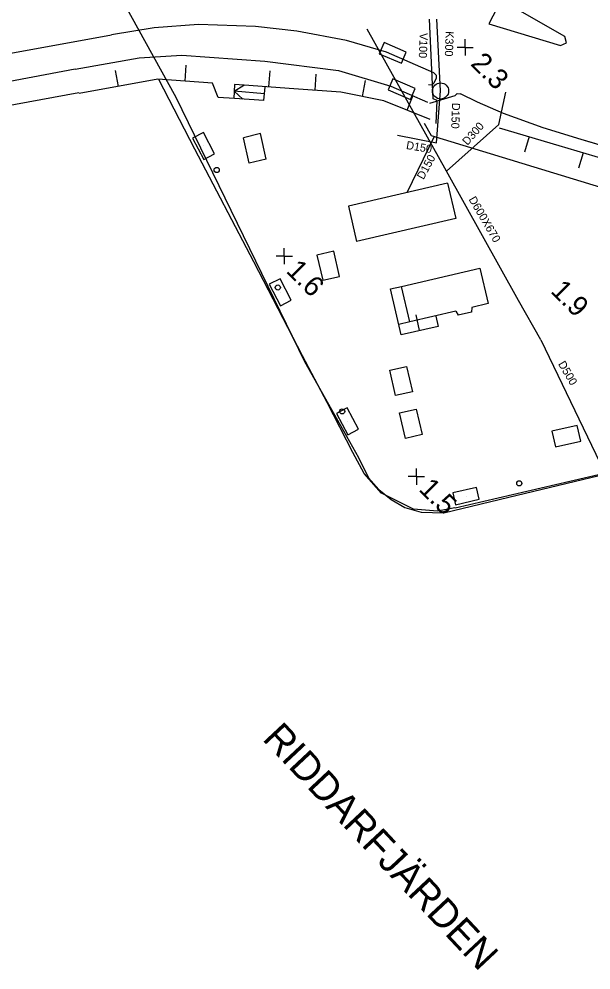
# Model space of a CAD drawing. Extents: x 1596643 to 1597288, y 13057194 to 13057957.
# Drawn here: x 1596788 to 1596858.8, y 13057321.4 to 13057439.2 of the extents above; entities that cross this region are included whole.
import ezdxf

# ---------------------------------------------------------------- set-up
doc = ezdxf.new("R2010")
doc.units = 0
for name, color, linetype in [('BAS bro ej def L', 7, 'Continuous'), ('BAS byggnad anläggning L', 7, 'Continuous'), ('BAS dagvatten brunn P', 7, 'Continuous'), ('BAS dagvatten ledning L', 7, 'Continuous'), ('BAS dagvatten ledning T', 7, 'Continuous'), ('BAS fastighetsgräns samfällighet L', 7, 'Continuous'), ('BAS kajkant L', 7, 'Continuous'), ('BAS Level 16', 7, 'Continuous'), ('BAS Level 18', 7, 'Continuous'), ('BAS Level 29', 7, 'Continuous'), ('BAS Level 34', 7, 'Continuous'), ('BAS markytetext T', 7, 'Continuous'), ('BAS spillvatten nedst brunn P', 7, 'Continuous'), ('BAS stödmur krön L', 7, 'Continuous'), ('BAS trappa L', 7, 'Continuous'), ('BAS vatten ledning L', 7, 'Continuous'), ('BAS vatten ledning T', 7, 'Continuous'), ('BAS vägbanekant L', 7, 'Continuous'), ('D el-anläggning ej def L', 7, 'Continuous')]:
    doc.layers.add(name, color=color, linetype=linetype)

msp = doc.modelspace()

# ---------------------------------------------------------------- linework, layer by layer
at = {"layer": 'BAS bro ej def L'}
msp.add_lwpolyline([(1596705.32, 13057413.45), (1596795.42, 13057430.04)], dxfattribs=at)
at = {"layer": 'BAS byggnad anläggning L'}
for p, q in [((1596817.89, 13057424.96), (1596815.8, 13057424.46)), ((1596816.51, 13057421.31), (1596815.8, 13057424.46)), ((1596818.61, 13057421.81), (1596817.89, 13057424.96)), ((1596818.61, 13057421.81), (1596816.51, 13057421.31)), ((1596841.05, 13057418.83), (1596828.79, 13057415.97)), ((1596841.05, 13057418.83), (1596842.07, 13057414.46)), ((1596828.79, 13057415.97), (1596829.8, 13057411.6)), ((1596842.07, 13057414.46), (1596829.8, 13057411.6)), ((1596826.97, 13057410.42), (1596824.87, 13057409.93)), ((1596827.67, 13057407.28), (1596826.97, 13057410.42)), ((1596824.87, 13057409.93), (1596825.6, 13057406.82)), ((1596835.34, 13057406.04), (1596845.06, 13057408.29)), ((1596845.06, 13057408.29), (1596846.07, 13057403.92)), ((1596825.6, 13057406.82), (1596827.67, 13057407.28)), ((1596836.37, 13057401.67), (1596835.34, 13057406.04)), ((1596842.06, 13057402.98), (1596836.37, 13057401.67)), ((1596842.06, 13057402.98), (1596842.37, 13057402.48)), ((1596844.06, 13057403.44), (1596844, 13057402.86)), ((1596846.07, 13057403.92), (1596844.06, 13057403.44)), ((1596844, 13057402.86), (1596842.37, 13057402.48)), ((1596833.89, 13057395.67), (1596835.97, 13057396.13)), ((1596835.97, 13057396.13), (1596836.7, 13057393.01)), ((1596834.61, 13057392.52), (1596833.89, 13057395.67)), ((1596836.7, 13057393.01), (1596834.61, 13057392.52)), ((1596835.11, 13057390.39), (1596837.18, 13057390.86)), ((1596835.86, 13057387.23), (1596835.11, 13057390.39)), ((1596837.18, 13057390.86), (1596837.92, 13057387.73)), ((1596857.09, 13057388.82), (1596853.98, 13057388.11)), ((1596857.53, 13057386.89), (1596857.09, 13057388.82)), ((1596837.92, 13057387.73), (1596835.86, 13057387.23)), ((1596853.98, 13057388.11), (1596854.42, 13057386.17)), ((1596854.42, 13057386.17), (1596857.53, 13057386.89))]:
    msp.add_line(p, q, dxfattribs=at)
msp.add_lwpolyline([(1596841.43, 13057417.48), (1596841.41, 13057417.48), (1596841.41, 13057417.46), (1596841.41, 13057417.5)], dxfattribs=at)
at = {"layer": 'BAS dagvatten brunn P'}
for p, q in [((1596834.27, 13057434.95), (1596834.27, 13057434.95)), ((1596834.27, 13057434.95), (1596834.27, 13057434.95)), ((1596835.38, 13057430.46), (1596835.38, 13057430.46)), ((1596835.38, 13057430.46), (1596835.38, 13057430.46)), ((1596810.86, 13057423.44), (1596810.86, 13057423.44)), ((1596810.86, 13057423.44), (1596810.86, 13057423.44)), ((1596820.35, 13057405.33), (1596820.35, 13057405.33)), ((1596820.35, 13057405.33), (1596820.35, 13057405.33)), ((1596828.67, 13057389.35), (1596828.67, 13057389.35)), ((1596828.67, 13057389.35), (1596828.67, 13057389.35)), ((1596843.34, 13057380.09), (1596843.34, 13057380.09)), ((1596843.34, 13057380.09), (1596843.34, 13057380.09))]:
    msp.add_line(p, q, dxfattribs=at)
for points in [[(1596832.59, 13057434.86), (1596835.34, 13057433.67), (1596835.94, 13057435.04), (1596833.19, 13057436.24)], [(1596832.59, 13057434.86), (1596835.34, 13057433.67), (1596835.94, 13057435.04), (1596833.19, 13057436.24)], [(1596833.7, 13057430.37), (1596836.45, 13057429.18), (1596837.05, 13057430.56), (1596834.3, 13057431.75)], [(1596833.7, 13057430.37), (1596836.45, 13057429.18), (1596837.05, 13057430.56), (1596834.3, 13057431.75)], [(1596809.5, 13057424.42), (1596810.89, 13057421.76), (1596812.22, 13057422.45), (1596810.83, 13057425.11)], [(1596809.5, 13057424.42), (1596810.89, 13057421.76), (1596812.22, 13057422.45), (1596810.83, 13057425.11)], [(1596818.99, 13057406.31), (1596820.38, 13057403.65), (1596821.71, 13057404.35), (1596820.32, 13057407)], [(1596818.99, 13057406.31), (1596820.38, 13057403.65), (1596821.71, 13057404.35), (1596820.32, 13057407)], [(1596827.31, 13057390.33), (1596828.7, 13057387.67), (1596830.03, 13057388.37), (1596828.63, 13057391.03)], [(1596827.31, 13057390.33), (1596828.7, 13057387.67), (1596830.03, 13057388.37), (1596828.63, 13057391.03)], [(1596842.05, 13057379.02), (1596844.97, 13057379.7), (1596844.63, 13057381.16), (1596841.71, 13057380.48)], [(1596842.05, 13057379.02), (1596844.97, 13057379.7), (1596844.63, 13057381.16), (1596841.71, 13057380.48)]]:
    msp.add_lwpolyline(points, close=True, dxfattribs=at)
at = {"layer": 'BAS dagvatten ledning L'}
for p, q in [((1596840.19, 13057430.25), (1596839.73, 13057439.12)), ((1596840.94, 13057420.31), (1596831.11, 13057437.9)), ((1596839.7, 13057423.82), (1596840.19, 13057430.25)), ((1596847.4, 13057426.1), (1596848.28, 13057430.11)), ((1596840.94, 13057420.31), (1596847.4, 13057426.1)), ((1596834.84, 13057424.78), (1596839.7, 13057423.82)), ((1596839.41, 13057424.59), (1596836.01, 13057417.65)), ((1596849.83, 13057404.31), (1596840.94, 13057420.31)), ((1596852.61, 13057399.43), (1596849.83, 13057404.31)), ((1596852.61, 13057399.43), (1596861.67, 13057380.52))]:
    msp.add_line(p, q, dxfattribs=at)
at = {"layer": 'BAS fastighetsgräns samfällighet L'}
for points in [[(1596791.17, 13057459.15), (1596794.26, 13057453.32), (1596807.42, 13057429.48), (1596823.36, 13057396.75), (1596830.03, 13057384.85), (1596831.28, 13057382.34)], [(1596831.28, 13057382.34), (1596832.53, 13057380.89), (1596834.08, 13057379.67), (1596835.78, 13057378.66), (1596837.8, 13057378.11), (1596840.58, 13057378.01), (1596848.65, 13057379.95), (1596867.92, 13057384.59)]]:
    msp.add_lwpolyline(points, dxfattribs=at)
at = {"layer": 'BAS kajkant L'}
for p, q in [((1596809.78, 13057423.04), (1596805.31, 13057431.66)), ((1596817.07, 13057409.1), (1596809.78, 13057423.04)), ((1596823.12, 13057397.47), (1596817.07, 13057409.1)), ((1596826.15, 13057391.69), (1596823.12, 13057397.47)), ((1596829.33, 13057385.5), (1596826.15, 13057391.69)), ((1596877.36, 13057386.83), (1596841.98, 13057378.6)), ((1596830.75, 13057382.88), (1596829.33, 13057385.5)), ((1596832.86, 13057380.46), (1596830.75, 13057382.88)), ((1596836.85, 13057378.45), (1596832.86, 13057380.46)), ((1596839.81, 13057378.23), (1596836.85, 13057378.45)), ((1596841.97, 13057378.62), (1596839.81, 13057378.23))]:
    msp.add_line(p, q, dxfattribs=at)
at = {"layer": 'BAS Level 16'}
for p, q in [((1596843.24, 13057435.64), (1596843.24, 13057436.64)), ((1596843.24, 13057435.64), (1596843.24, 13057436.64)), ((1596843.24, 13057435.64), (1596842.24, 13057435.64)), ((1596843.24, 13057435.64), (1596842.24, 13057435.64)), ((1596843.24, 13057435.64), (1596844.24, 13057435.64)), ((1596843.24, 13057435.64), (1596843.24, 13057434.64)), ((1596843.24, 13057435.64), (1596844.24, 13057435.64)), ((1596843.24, 13057435.64), (1596843.24, 13057434.64)), ((1596820.85, 13057409.79), (1596820.85, 13057410.79)), ((1596820.85, 13057409.79), (1596820.85, 13057410.79)), ((1596820.85, 13057409.79), (1596819.85, 13057409.79)), ((1596820.85, 13057409.79), (1596819.85, 13057409.79)), ((1596820.85, 13057409.79), (1596821.85, 13057409.79)), ((1596820.85, 13057409.79), (1596820.85, 13057408.79)), ((1596820.85, 13057409.79), (1596821.85, 13057409.79)), ((1596820.85, 13057409.79), (1596820.85, 13057408.79)), ((1596837.19, 13057382.49), (1596837.19, 13057383.49)), ((1596837.19, 13057382.49), (1596837.19, 13057383.49)), ((1596837.19, 13057382.49), (1596836.19, 13057382.49)), ((1596837.19, 13057382.49), (1596836.19, 13057382.49)), ((1596837.19, 13057382.49), (1596838.19, 13057382.49)), ((1596837.19, 13057382.49), (1596837.19, 13057381.49)), ((1596837.19, 13057382.49), (1596838.19, 13057382.49)), ((1596837.19, 13057382.49), (1596837.19, 13057381.49))]:
    msp.add_line(p, q, dxfattribs=at)
at = {"layer": 'BAS Level 18'}
for p, q in [((1596800.32, 13057430.81), (1596799.97, 13057432.78)), ((1596800.32, 13057430.81), (1596799.97, 13057432.78)), ((1596808.59, 13057431.46), (1596808.72, 13057433.46)), ((1596808.59, 13057431.46), (1596808.72, 13057433.46)), ((1596818.94, 13057430.74), (1596819.08, 13057432.74)), ((1596818.94, 13057430.74), (1596819.08, 13057432.74)), ((1596824.65, 13057430.34), (1596824.79, 13057432.33)), ((1596824.65, 13057430.34), (1596824.79, 13057432.33)), ((1596830.51, 13057429.57), (1596830.91, 13057431.53)), ((1596830.51, 13057429.57), (1596830.91, 13057431.53)), ((1596836.04, 13057427.87), (1596836.79, 13057429.73)), ((1596836.04, 13057427.87), (1596836.79, 13057429.73)), ((1596851.14, 13057424.59), (1596850.58, 13057422.68)), ((1596851.14, 13057424.59), (1596850.58, 13057422.68)), ((1596857.85, 13057422.6), (1596857.27, 13057420.69)), ((1596857.85, 13057422.6), (1596857.27, 13057420.69)), ((1596837.6, 13057400.58), (1596837.17, 13057402.53)), ((1596837.6, 13057400.58), (1596837.17, 13057402.53))]:
    msp.add_line(p, q, dxfattribs=at)
at = {"layer": 'BAS Level 29'}
for centre in [(1596812.48, 13057420.46), (1596812.48, 13057420.46), (1596820.04, 13057405.91), (1596820.04, 13057405.91), (1596828.01, 13057390.57), (1596828.01, 13057390.57), (1596849.93, 13057381.66), (1596849.93, 13057381.66)]:
    msp.add_circle(centre, 0.318, dxfattribs=at)
at = {"layer": 'BAS spillvatten nedst brunn P'}
msp.add_circle((1596840.19, 13057430.25), 1, dxfattribs=at)
msp.add_circle((1596840.19, 13057430.25), 1, dxfattribs=at)
at = {"layer": 'BAS stödmur krön L'}
for p, q in [((1596805.19, 13057431.69), (1596795.45, 13057429.93)), ((1596811.98, 13057431.23), (1596805.19, 13057431.69)), ((1596812.67, 13057429.45), (1596811.98, 13057431.23)), ((1596816.44, 13057430.92), (1596814.69, 13057431.04)), ((1596821.44, 13057430.56), (1596816.44, 13057430.92)), ((1596827.86, 13057430.11), (1596821.44, 13057430.56)), ((1596833.16, 13057429.03), (1596827.86, 13057430.11)), ((1596814.67, 13057429.33), (1596812.67, 13057429.45)), ((1596838.91, 13057426.71), (1596833.16, 13057429.03)), ((1596847.44, 13057425.68), (1596854.84, 13057423.51)), ((1596854.84, 13057423.51), (1596870.42, 13057418.81)), ((1596834, 13057405.73), (1596835.34, 13057406.04)), ((1596835.3, 13057400.07), (1596834, 13057405.73)), ((1596839.61, 13057402.37), (1596839.89, 13057401.09)), ((1596836.37, 13057401.67), (1596835.01, 13057401.33)), ((1596839.89, 13057401.09), (1596835.3, 13057400.07))]:
    msp.add_line(p, q, dxfattribs=at)
at = {"layer": 'BAS trappa L'}
for p, q in [((1596814.69, 13057431.04), (1596814.59, 13057429.33)), ((1596814.64, 13057430.21), (1596815.84, 13057430.96)), ((1596818.4, 13057429.88), (1596814.64, 13057430.21)), ((1596814.64, 13057430.21), (1596815.72, 13057429.25)), ((1596818.3, 13057429.07), (1596818.5, 13057430.77)), ((1596818.3, 13057429.07), (1596814.67, 13057429.33))]:
    msp.add_line(p, q, dxfattribs=at)
at = {"layer": 'BAS vatten ledning L'}
for p, q in [((1596839.28, 13057429.28), (1596838.82, 13057439.12)), ((1596839.77, 13057429.06), (1596839.28, 13057429.28)), ((1596839.63, 13057426.21), (1596839.77, 13057429.06)), ((1596839.08, 13057424.69), (1596838.2, 13057426.23)), ((1596882.75, 13057411.3), (1596839.08, 13057424.69))]:
    msp.add_line(p, q, dxfattribs=at)
at = {"layer": 'BAS vägbanekant L'}
for p, q in [((1596847.71, 13057441.55), (1596846.15, 13057438.54)), ((1596855.55, 13057436.99), (1596847.71, 13057441.55)), ((1596810.22, 13057438.47), (1596804.73, 13057438.05)), ((1596817.3, 13057438.24), (1596810.22, 13057438.47)), ((1596846.15, 13057438.54), (1596855.02, 13057435.88)), ((1596804.73, 13057438.05), (1596799.46, 13057437.21)), ((1596822.39, 13057437.65), (1596817.3, 13057438.24)), ((1596828.55, 13057436.49), (1596822.39, 13057437.65)), ((1596833.5, 13057435.03), (1596828.55, 13057436.49)), ((1596855.02, 13057435.88), (1596855.79, 13057436.19)), ((1596855.79, 13057436.19), (1596855.55, 13057436.99)), ((1596839.34, 13057432.48), (1596833.5, 13057435.03)), ((1596794.96, 13057432.93), (1596802.87, 13057434.35)), ((1596802.87, 13057434.35), (1596808.16, 13057434.69)), ((1596808.16, 13057434.69), (1596818.43, 13057433.94)), ((1596818.43, 13057433.94), (1596827.57, 13057432.79)), ((1596827.57, 13057432.79), (1596834.02, 13057430.82)), ((1596839.34, 13057432.48), (1596839.63, 13057432.2)), ((1596839.36, 13057431.22), (1596839.12, 13057430.98)), ((1596839.63, 13057431.83), (1596839.36, 13057431.22)), ((1596839.63, 13057432.2), (1596839.63, 13057431.83)), ((1596834.02, 13057430.82), (1596838.57, 13057428.85)), ((1596839.12, 13057430.98), (1596838.71, 13057431.02)), ((1596842, 13057429.7), (1596842.23, 13057429.93)), ((1596842.23, 13057429.93), (1596842.64, 13057429.91)), ((1596844.78, 13057428.87), (1596842.64, 13057429.91)), ((1596847.98, 13057427.47), (1596844.78, 13057428.87)), ((1596852.89, 13057425.67), (1596847.98, 13057427.47)), ((1596857.58, 13057424.25), (1596852.89, 13057425.67)), ((1596862.29, 13057422.83), (1596857.58, 13057424.25))]:
    msp.add_line(p, q, dxfattribs=at)
for points in [[(1596847.71, 13057441.55), (1596846.15, 13057438.54)], [(1596855.55, 13057436.99), (1596847.71, 13057441.55)], [(1596810.22, 13057438.47), (1596804.73, 13057438.05)], [(1596817.3, 13057438.24), (1596810.22, 13057438.47)], [(1596846.15, 13057438.54), (1596855.02, 13057435.88)], [(1596704.62, 13057419.96), (1596799.46, 13057437.21)], [(1596804.73, 13057438.05), (1596799.46, 13057437.21)], [(1596822.39, 13057437.65), (1596817.3, 13057438.24)], [(1596828.55, 13057436.49), (1596822.39, 13057437.65)], [(1596833.5, 13057435.03), (1596828.55, 13057436.49)], [(1596855.02, 13057435.88), (1596855.79, 13057436.19)], [(1596855.79, 13057436.19), (1596855.55, 13057436.99)], [(1596839.34, 13057432.48), (1596833.5, 13057435.03)], [(1596794.96, 13057432.93), (1596802.87, 13057434.35)], [(1596802.87, 13057434.35), (1596808.16, 13057434.69)], [(1596808.16, 13057434.69), (1596818.43, 13057433.94)], [(1596818.43, 13057433.94), (1596827.57, 13057432.79)], [(1596794.96, 13057432.93), (1596774.16, 13057429.01)], [(1596827.57, 13057432.79), (1596834.02, 13057430.82)], [(1596839.34, 13057432.48), (1596839.63, 13057432.2)], [(1596839.36, 13057431.22), (1596839.12, 13057430.98)], [(1596839.63, 13057431.83), (1596839.36, 13057431.22)], [(1596839.63, 13057432.2), (1596839.63, 13057431.83)], [(1596834.02, 13057430.82), (1596838.57, 13057428.85)], [(1596839.12, 13057430.98), (1596838.71, 13057431.02)], [(1596842.13, 13057429.8), (1596841.96, 13057429.65), (1596838.83, 13057428.69)], [(1596842, 13057429.7), (1596842.23, 13057429.93)], [(1596842.23, 13057429.93), (1596842.64, 13057429.91)], [(1596844.78, 13057428.87), (1596842.64, 13057429.91)], [(1596847.98, 13057427.47), (1596844.78, 13057428.87)], [(1596852.89, 13057425.67), (1596847.98, 13057427.47)], [(1596857.58, 13057424.25), (1596852.89, 13057425.67)], [(1596862.29, 13057422.83), (1596857.58, 13057424.25)]]:
    msp.add_lwpolyline(points, dxfattribs=at)
at = {"layer": 'D el-anläggning ej def L'}
msp.add_circle((1596849.93, 13057381.66), 0.318, dxfattribs=at)
msp.add_circle((1596849.93, 13057381.66), 0.318, dxfattribs=at)

# ---------------------------------------------------------------- texts
at = {"layer": 'BAS dagvatten ledning T'}
for s, rotation, p in [('K300', 267.8605, (1596840.83, 13057437.66)), ('D150', 267.8605, (1596841.62, 13057428.79)), ('D300', 48.4817, (1596843.52, 13057423.44)), ('D150', 350.5311, (1596835.88, 13057423.07)), ('D150', 61.345, (1596838.07, 13057419.2)), ('D600X670', 300.298, (1596843.63, 13057416.83)), ('D500', 300.298, (1596854.7, 13057396.45))]:
    msp.add_text(s, height=1, rotation=rotation, dxfattribs=at).set_placement(p)
at = {"layer": 'BAS Level 34'}
msp.add_text('RIDDARFJÄRDEN', height=3.499, rotation=313.1313, dxfattribs=at).set_placement((1596818.03, 13057349.96))
at = {"layer": 'BAS markytetext T'}
for s, p in [('2.3', (1596843.8, 13057433.51)), ('1.6', (1596820.96, 13057407.86)), ('1.9', (1596853.7, 13057405.36)), ('1.5', (1596837.38, 13057380.82))]:
    msp.add_text(s, height=2.5, rotation=315, dxfattribs=at).set_placement(p)
at = {"layer": 'BAS vatten ledning T'}
msp.add_text('V100', height=1, rotation=267.8605, dxfattribs=at).set_placement((1596837.61, 13057437.45))

doc.saveas('drawing.dxf')
